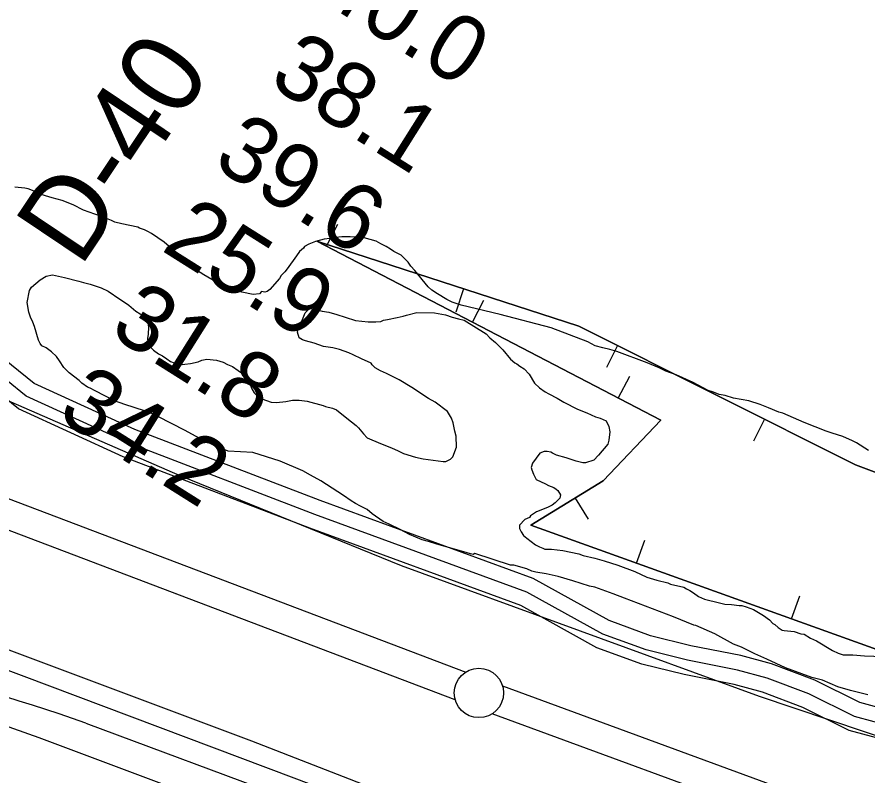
# Model space of a CAD drawing. Extents: x 3279314 to 3317160, y 734079 to 759431.
# Drawn here: x 3286993 to 3287854, y 752273 to 753041 of the extents above; entities that cross this region are included whole.
import ezdxf

# ---------------------------------------------------------------- set-up
doc = ezdxf.new("R2010")
doc.units = 0
for name, color, linetype in [('V-BORW-LINE', 7, 'Continuous'), ('V-LEVE-TOET', 7, 'Continuous'), ('V-RIVR-RANG', 7, 'Continuous'), ('V-RIVR-RANG-IDEN', 7, 'Continuous'), ('V-ROAD-CNTR', 7, 'Continuous'), ('V-SITE-VEGE', 7, 'Continuous'), ('V-SURV-LINE', 7, 'Continuous'), ('V-TOPO-SHOR', 7, 'Continuous')]:
    doc.layers.add(name, color=color, linetype=linetype)

msp = doc.modelspace()

# ---------------------------------------------------------------- linework, layer by layer
at = {"layer": 'V-BORW-LINE'}
for p, q in [((3287306.5, 752809.39), (3287318.04, 752831.57)), ((3287445.27, 752766.29), (3287437.56, 752742.51)), ((3287454.31, 752732.52), (3287465.84, 752754.7)), ((3287601.25, 752708.84), (3287590.06, 752686.48)), ((3287602.12, 752655.65), (3287613.65, 752677.83)), ((3287750.23, 752634.25), (3287739.03, 752611.89)), ((3287558.57, 752554.49), (3287571.64, 752533.17)), ((3287620.63, 752488.43), (3287629.08, 752511.96)), ((3287777.43, 752432.13), (3287785.88, 752455.66))]:
    msp.add_line(p, q, dxfattribs=at)
for points in [[(3288076.22, 752324.85), (3287513.54, 752526.89), (3287586.76, 752571.77), (3287645.31, 752633.19), (3287296.98, 752814.34), (3287562.12, 752728.43), (3287842.27, 752588.16), (3288177.37, 752462.36)], [(3288177.37, 752462.36), (3287842.27, 752588.16), (3287562.12, 752728.43), (3287296.98, 752814.34), (3287645.31, 752633.19), (3287586.76, 752571.77), (3287513.54, 752526.89), (3288076.22, 752324.85)]]:
    msp.add_lwpolyline(points, dxfattribs=at)
at = {"layer": 'V-LEVE-TOET'}
for points in [[(3288101.29, 752234.06), (3287744.97, 752353.62), (3287382.47, 752485.9), (3287158.35, 752576.77), (3286947.55, 752668.83), (3286901.98, 752681.34), (3286833.62, 752701.5), (3286800.83, 752711.3), (3286692.59, 752719.58), (3286381.21, 752738.4), (3286226.37, 752743.1), (3286159.25, 752739.95), (3286140.93, 752741.52), (3286104.85, 752744.09), (3286070.41, 752751.67), (3285922.69, 752773.61), (3285827.68, 752796.39), (3285718.72, 752834.63), (3285638.05, 752873.03), (3285594.62, 752899.98), (3285563.98, 752923.67), (3285516.62, 752957.81), (3285423.37, 753064.94), (3285301.93, 753253.48)], [(3285262.75, 752889.6), (3285343.06, 752815.69), (3285429.43, 752748.47), (3285528.48, 752696.86), (3285666.46, 752629.37), (3285783.78, 752586.18), (3285881.03, 752558.97), (3285992.11, 752539.05), (3286172.02, 752515.63), (3286527.76, 752488.39), (3286550.6, 752486.64), (3286717.13, 752473.69), (3286780.99, 752464.6), (3286828.21, 752454.88), (3286982.19, 752401.9), (3287230.73, 752308.94), (3287573.27, 752175.44)]]:
    msp.add_lwpolyline(points, dxfattribs=at)
at = {"layer": 'V-ROAD-CNTR'}
for points in [[(3287885.04, 752337.21), (3287846.56, 752347.55), (3287800.95, 752370.04), (3287757.32, 752386.63), (3287726.12, 752395.01), (3287675.45, 752405.08), (3287634.55, 752415.19), (3287592.8, 752430.41), (3287515.8, 752473.08), (3287300.2, 752551.92), (3287112.53, 752623.92), (3287010.64, 752670.39), (3286971.48, 752701.83), (3286946.67, 752719.05)], [(3287881.12, 752322.73), (3287841.25, 752333.44), (3287794.96, 752356.27), (3287752.7, 752372.34), (3287722.71, 752380.39), (3287672.18, 752390.43), (3287630.17, 752400.83), (3287586.55, 752416.72), (3287509.55, 752459.39), (3287294.94, 752537.87), (3287106.72, 752610.08), (3287002.71, 752657.52), (3286962.5, 752689.81), (3286925.29, 752715.63)], [(3287881.12, 752322.73), (3287841.25, 752333.44), (3287794.96, 752356.27), (3287752.7, 752372.34), (3287722.71, 752380.39), (3287672.18, 752390.43), (3287630.17, 752400.83), (3287586.55, 752416.72), (3287509.55, 752459.39), (3287294.94, 752537.87), (3287106.72, 752610.08), (3287002.71, 752657.52), (3286962.5, 752689.81), (3286925.29, 752715.63)], [(3287877.2, 752308.25), (3287835.93, 752319.34), (3287788.96, 752342.5), (3287748.08, 752358.05), (3287719.3, 752365.78), (3287668.92, 752375.79), (3287625.78, 752386.46), (3287580.31, 752403.03), (3287503.3, 752445.71), (3287289.68, 752523.83), (3287100.92, 752596.24), (3286994.78, 752644.65), (3286953.52, 752677.78), (3286920.84, 752700.46)], [(3287063.04, 752326.83), (3287267.8, 752250.43), (3287686.25, 752095.63), (3288047.69, 751959.45), (3288483.21, 751793.21), (3289271.48, 751500.19), (3289390.29, 751454.85), (3289479.01, 751419.83), (3289543.51, 751393.45), (3289598.16, 751371.77), (3289712.35, 751320.09), (3290928.13, 750767.33), (3291722.58, 750405.5), (3291886.96, 750335.48), (3291919.9, 750322.09), (3291955.61, 750310.52), (3291986.73, 750299.9), (3292011.96, 750294.14), (3292042.37, 750286.9), (3292074.59, 750280.07), (3292105.59, 750274.89), (3292168.37, 750265.25), (3292338.95, 750247.98), (3294136.95, 750064.8)]]:
    msp.add_lwpolyline(points, dxfattribs=at)
msp.add_arc((3286455.47, 750596.15), 1834.22, 70.65572, 84.8569, dxfattribs=at)
at = {"layer": 'V-SITE-VEGE'}
for points in [[(3287082.31, 752837.93), (3287077.87, 752839.57), (3287060.64, 752845.58), (3287050.06, 752851.07), (3287038.94, 752855.45), (3287028.94, 752858.17), (3287022.27, 752860.35), (3287014.48, 752863.08), (3287012.26, 752864.18), (3287004.47, 752867.46), (3287001.14, 752868), (3286991.15, 752869.06)], [(3287855.43, 752602.48), (3287843.18, 752610.18), (3287839.29, 752612.38), (3287829.27, 752616.77), (3287818.72, 752620.04), (3287812.6, 752622.22), (3287790.35, 752630.98), (3287768.66, 752640.29), (3287764.77, 752641.38), (3287754.21, 752645.76), (3287745.87, 752649.04), (3287734.19, 752652.87), (3287718.64, 752655.55), (3287710.3, 752658.28), (3287704.19, 752659.36), (3287698.63, 752661.55), (3287693.08, 752663.18), (3287678.05, 752671.42), (3287660.81, 752679.09), (3287650.24, 752682.92), (3287643.56, 752686.21), (3287631.33, 752691.14), (3287600.75, 752702.62), (3287593.53, 752704.8), (3287586.3, 752706.43), (3287578.52, 752708.6), (3287571.29, 752712.45), (3287534.04, 752726.67), (3287482.36, 752740.26), (3287442.91, 752749.47), (3287434.02, 752752.75), (3287428.45, 752755.49), (3287418.99, 752760.99), (3287413.42, 752764.84), (3287409.52, 752768.15), (3287396.11, 752784.72), (3287392.2, 752789.14), (3287389.4, 752793.01), (3287382.15, 752800.19), (3287374.92, 752804.03), (3287371.58, 752806.23), (3287367.12, 752808.98), (3287361.56, 752811.72), (3287357.1, 752814.47), (3287344.88, 752817.73), (3287330.45, 752818.77), (3287322.12, 752818.72), (3287316.02, 752818.13), (3287309.93, 752816.99), (3287304.38, 752816.4), (3287295.52, 752814.14), (3287288.87, 752811.32), (3287284.45, 752809.08), (3287283.34, 752807.41), (3287279.48, 752804.06), (3287276.17, 752799.6), (3287266.81, 752786.23), (3287264.61, 752783.45), (3287260.75, 752779.54), (3287259.1, 752776.76), (3287249.17, 752765.6), (3287246.41, 752763.37), (3287244.2, 752762.8), (3287240.86, 752763.34), (3287238.66, 752761.11), (3287232.56, 752760.52), (3287220.89, 752762.68), (3287215.33, 752764.31), (3287209.22, 752766.5), (3287203.66, 752768.68), (3287194.76, 752773.07), (3287182.51, 752780.22), (3287172.48, 752786.82), (3287164.68, 752793.99), (3287159.1, 752798.95), (3287142.38, 752813.29), (3287129.57, 752822.1), (3287125.67, 752824.3), (3287122.33, 752825.95), (3287117.33, 752827.58), (3287115.66, 752828.68), (3287099.55, 752831.92), (3287092.33, 752833.55), (3287088.99, 752835.19), (3287082.31, 752837.93)], [(3287177.56, 752615.17), (3287163.65, 752622.86), (3287135.83, 752637.13), (3287131.93, 752639.33), (3287122.48, 752642.61), (3287102.47, 752649.15), (3287091.9, 752652.98), (3287072.43, 752662.86), (3287067.42, 752665.61), (3287064.64, 752666.7), (3287059.07, 752670.56), (3287056.28, 752673.31), (3287046.25, 752681.03), (3287040.67, 752686.54), (3287036.2, 752693.18), (3287033.4, 752697.6), (3287028.38, 752702.57), (3287022.81, 752706.42), (3287018.36, 752708.62), (3287016.68, 752710.83), (3287015, 752714.15), (3287011.03, 752728), (3287009.35, 752732.43), (3287007.1, 752737.41), (3287005.41, 752742.39), (3287003.69, 752752.37), (3287005.84, 752764.59), (3287008.04, 752767.93), (3287016.88, 752775.19), (3287022.96, 752779.11), (3287029.06, 752780.25), (3287041.28, 752777.55), (3287055.73, 752773.74), (3287060.73, 752772.66), (3287067.4, 752771.03), (3287073.51, 752768.84), (3287078.51, 752767.21), (3287085.75, 752763.92), (3287097.44, 752755.66), (3287100.23, 752754.01), (3287106.35, 752749.61), (3287113.6, 752743.54), (3287118.05, 752740.79), (3287125.87, 752732.51), (3287126.45, 752727.52), (3287125.94, 752720.31), (3287125.41, 752715.86), (3287125.99, 752710.32), (3287127.11, 752708.66), (3287131.57, 752704.24), (3287136.59, 752700.39), (3287140.48, 752698.19), (3287144.94, 752695.44), (3287148.84, 752692.69), (3287156.06, 752689.95), (3287160.51, 752689.42), (3287163.28, 752689.99), (3287168.82, 752690.58), (3287176.58, 752692.29), (3287180.46, 752693.97), (3287185.45, 752695.11), (3287195.44, 752694.05), (3287202.11, 752691.87), (3287206.56, 752689.68), (3287211.56, 752687.49), (3287217.14, 752683.63), (3287221.59, 752680.33), (3287228.3, 752672.04), (3287231.11, 752664.84), (3287233.35, 752660.97), (3287236.7, 752657.66), (3287241.15, 752654.91), (3287250.6, 752651.63), (3287256.16, 752651.11), (3287265.58, 752652.27), (3287272.23, 752653.42), (3287278.89, 752653.45), (3287287.22, 752652.39), (3287303.34, 752648.04), (3287305.56, 752646.94), (3287312.78, 752645.32), (3287316.68, 752643.68), (3287327.26, 752635.41), (3287336.74, 752627.7), (3287338.97, 752625.49), (3287342.32, 752621.62), (3287344, 752619.41), (3287347.9, 752615.55), (3287361.25, 752609.52), (3287372.38, 752605.14), (3287379.05, 752602.4), (3287384.61, 752599.66), (3287396.84, 752595.84), (3287404.62, 752594.22), (3287424.61, 752591.56), (3287427.38, 752591.57), (3287432.36, 752593.82), (3287434.57, 752596.05), (3287438.4, 752606.06), (3287437.78, 752617.15), (3287436.65, 752622.14)], [(3287282.87, 752736.71), (3287285.06, 752741.71), (3287289.48, 752746.18), (3287294.48, 752745.65), (3287302.26, 752743.47), (3287308.92, 752742.4), (3287317.25, 752740.22), (3287325.59, 752737.49), (3287336.15, 752734.23), (3287348.92, 752732.63), (3287356.69, 752732.67), (3287361.68, 752733.26), (3287364.45, 752734.38), (3287368.33, 752734.96), (3287378.31, 752737.23), (3287384.4, 752738.38), (3287387.73, 752739.5), (3287398.25, 752742.34), (3287416.01, 752741.88), (3287427.12, 752739.72), (3287433.79, 752737.54), (3287440.46, 752735.91), (3287446.02, 752734.28), (3287468.29, 752720.53), (3287472.19, 752716.66), (3287477.77, 752711.7), (3287485.02, 752704.53), (3287492.84, 752695.14), (3287497.3, 752691.28), (3287499.53, 752690.18), (3287502.31, 752687.98), (3287506.77, 752685.23), (3287511.79, 752679.71), (3287517.39, 752670.86), (3287522.41, 752665.89), (3287527.98, 752662.04), (3287531.88, 752659.84), (3287540.22, 752655.45), (3287546.9, 752651.6), (3287560.81, 752644.46), (3287570.27, 752640.63), (3287579.16, 752636.8), (3287583.61, 752635.16), (3287589.73, 752632.42), (3287592.54, 752626.88), (3287593.68, 752621.34), (3287592.61, 752613.01), (3287591.52, 752609.12), (3287582.15, 752597.97), (3287577.19, 752592.95), (3287568.88, 752590.13), (3287566.11, 752590.12), (3287559.44, 752591.74), (3287549.43, 752595.02), (3287539.43, 752597.74), (3287535.54, 752599.94), (3287533.86, 752601.04), (3287529.98, 752601.57), (3287527.2, 752601.55), (3287522.77, 752599.86), (3287515.06, 752589.83), (3287513.98, 752585.39), (3287514.54, 752583.17), (3287516.23, 752578.74), (3287519.04, 752573.21), (3287528.49, 752568.83), (3287531.27, 752567.17), (3287536.84, 752564.98), (3287539.07, 752563.33), (3287540.73, 752562.23), (3287543.54, 752557.81), (3287543, 752554.48), (3287538.03, 752549.46), (3287535.27, 752547.22), (3287530.29, 752544.98), (3287519.22, 752540.47), (3287515.35, 752537.68), (3287513.13, 752536.56), (3287512.03, 752534.89), (3287507.61, 752532.64), (3287502.09, 752527.06), (3287502.11, 752523.73), (3287503.79, 752520.41), (3287506.03, 752516.54), (3287509.38, 752513.79), (3287518.29, 752507.18), (3287522.19, 752504.98), (3287525.52, 752503.89), (3287527.75, 752502.79), (3287534.41, 752502.83), (3287546.07, 752501.23), (3287562.18, 752497.99), (3287566.62, 752496.35), (3287578.29, 752493.64), (3287587.74, 752490.92), (3287601.63, 752486.55), (3287618.87, 752479.99), (3287631.11, 752474.51), (3287641.11, 752471.23), (3287652.22, 752468.52), (3287655, 752467.42)], [(3287436.65, 752622.14), (3287434.94, 752630.45), (3287433.24, 752635.44), (3287429.32, 752642.08), (3287416.51, 752651.44), (3287409.83, 752655.29), (3287393.12, 752666.29), (3287380.32, 752673.99), (3287367.52, 752680.58), (3287361.4, 752683.32), (3287355.84, 752686.06), (3287353.05, 752689.37), (3287351.93, 752691.03), (3287341.92, 752695.42), (3287333.57, 752699.26), (3287329.12, 752701.45), (3287319.67, 752704.73), (3287313, 752706.35), (3287303.56, 752707.97), (3287294.11, 752711.24), (3287285.22, 752713.42), (3287282.44, 752714.51), (3287279.1, 752716.71), (3287277.4, 752722.25), (3287277.94, 752725.58), (3287280.68, 752731.15), (3287282.87, 752736.71)], [(3287854.82, 752355.33), (3287837.04, 752359.67), (3287824.26, 752363.48), (3287808.69, 752370.06), (3287798.13, 752372.78), (3287771.44, 752382.62), (3287752.53, 752391.39), (3287740.29, 752396.87), (3287726.94, 752403.46), (3287718.6, 752406.74), (3287699.67, 752417.18), (3287680.76, 752425.4), (3287678.54, 752425.94), (3287657.96, 752434.15), (3287608.48, 752453.3), (3287596.8, 752457.67), (3287578.45, 752464.23), (3287572.9, 752465.31), (3287556.22, 752470.77), (3287541.22, 752475.12), (3287528.99, 752477.83), (3287518.44, 752479.44), (3287514.55, 752480.52), (3287509.55, 752482.72), (3287496.21, 752486.52), (3287492.88, 752486.51), (3287456.75, 752498.52), (3287455.09, 752497.4), (3287452.31, 752497.94), (3287445.64, 752500.12), (3287418.41, 752507.74), (3287410.07, 752510.46), (3287403.4, 752512.09), (3287390.61, 752517.57), (3287381.15, 752522.51), (3287370.03, 752528), (3287363.91, 752530.74), (3287352.77, 752538.45), (3287347.75, 752542.86), (3287341.07, 752546.15), (3287336.06, 752548.9), (3287331.61, 752551.65), (3287323.81, 752557.16), (3287300.98, 752572.01), (3287290.41, 752577.5), (3287282.62, 752581.9), (3287259.81, 752591.76), (3287232.02, 752600.48), (3287207.04, 752602.01), (3287190.91, 752608.58), (3287177.56, 752615.17)], [(3287655, 752467.42), (3287668.34, 752464.17), (3287671.12, 752462.52), (3287674.46, 752460.88), (3287678.36, 752458.68), (3287683.37, 752454.82), (3287689.49, 752452.08), (3287704.49, 752448.28), (3287710.05, 752447.2), (3287716.71, 752446.68), (3287724.48, 752445.61), (3287727.26, 752445.63), (3287731.7, 752444.54), (3287738.93, 752441.81), (3287748.95, 752435.76), (3287755.08, 752431.35), (3287758.43, 752427.49), (3287760.66, 752426.39), (3287764, 752423.64), (3287767.9, 752420.88), (3287770.12, 752420.34), (3287780.12, 752419.29), (3287786.79, 752417.1), (3287790.12, 752416.57), (3287796.8, 752412.72), (3287802.92, 752409.98), (3287819.06, 752400.08), (3287824.63, 752397.34), (3287829.63, 752395.7), (3287839.62, 752395.76), (3287851.27, 752394.71), (3287870.14, 752394.26)]]:
    msp.add_lwpolyline(points, dxfattribs=at)
at = {"layer": 'V-SURV-LINE'}
for points in [[(3286881.83, 752592.94), (3287447.57, 752378.35)], [(3287436.92, 752350.31), (3286871.18, 752564.89)], [(3287484.84, 752364.44), (3288711.76, 751913.69)], [(3288701.41, 751885.53), (3287474.49, 752336.28)]]:
    msp.add_lwpolyline(points, dxfattribs=at)
msp.add_circle((3287460.92, 752357.25), 25, dxfattribs=at)
at = {"layer": 'V-TOPO-SHOR'}
for points in [[(3286155, 752491.47), (3286470.06, 752458.84), (3286731.17, 752440.84), (3286808.05, 752428.2), (3286825.02, 752427.36), (3286839.95, 752425.02), (3286851.89, 752422.1), (3286903.05, 752408.76), (3286923.96, 752403.46), (3286944.32, 752395.74), (3286957.78, 752389.66), (3286971.23, 752384.89), (3287273.48, 752271.28), (3287456.37, 752202.15), (3287659.06, 752126.98), (3287864.75, 752046.79)], [(3287301.99, 752204.69), (3287015.8, 752311.86), (3286964.06, 752330.04), (3286931.19, 752341.79), (3286881.9, 752354.95), (3286822.35, 752368.25), (3286757.97, 752380.02), (3286669.17, 752389.81), (3286430.8, 752409.79)]]:
    msp.add_lwpolyline(points, dxfattribs=at)

# ---------------------------------------------------------------- texts
at = {"layer": 'V-RIVR-RANG'}
for s, p in [('40.0', (3287294.97, 753061.44)), ('38.1', (3287246.37, 752973.87)), ('39.6', (3287189.74, 752891.35)), ('25.9', (3287138.03, 752805.75)), ('31.8', (3287085.19, 752720.84)), ('34.2', (3287032.13, 752636.08))]:
    msp.add_text(s, height=67, rotation=327.81833, dxfattribs=at).set_placement(p)
at = {"layer": 'V-RIVR-RANG-IDEN'}
msp.add_text('D-40', height=83, rotation=56.13363, dxfattribs=at).set_placement((3287057.21, 752786.6))

doc.saveas('drawing.dxf')
